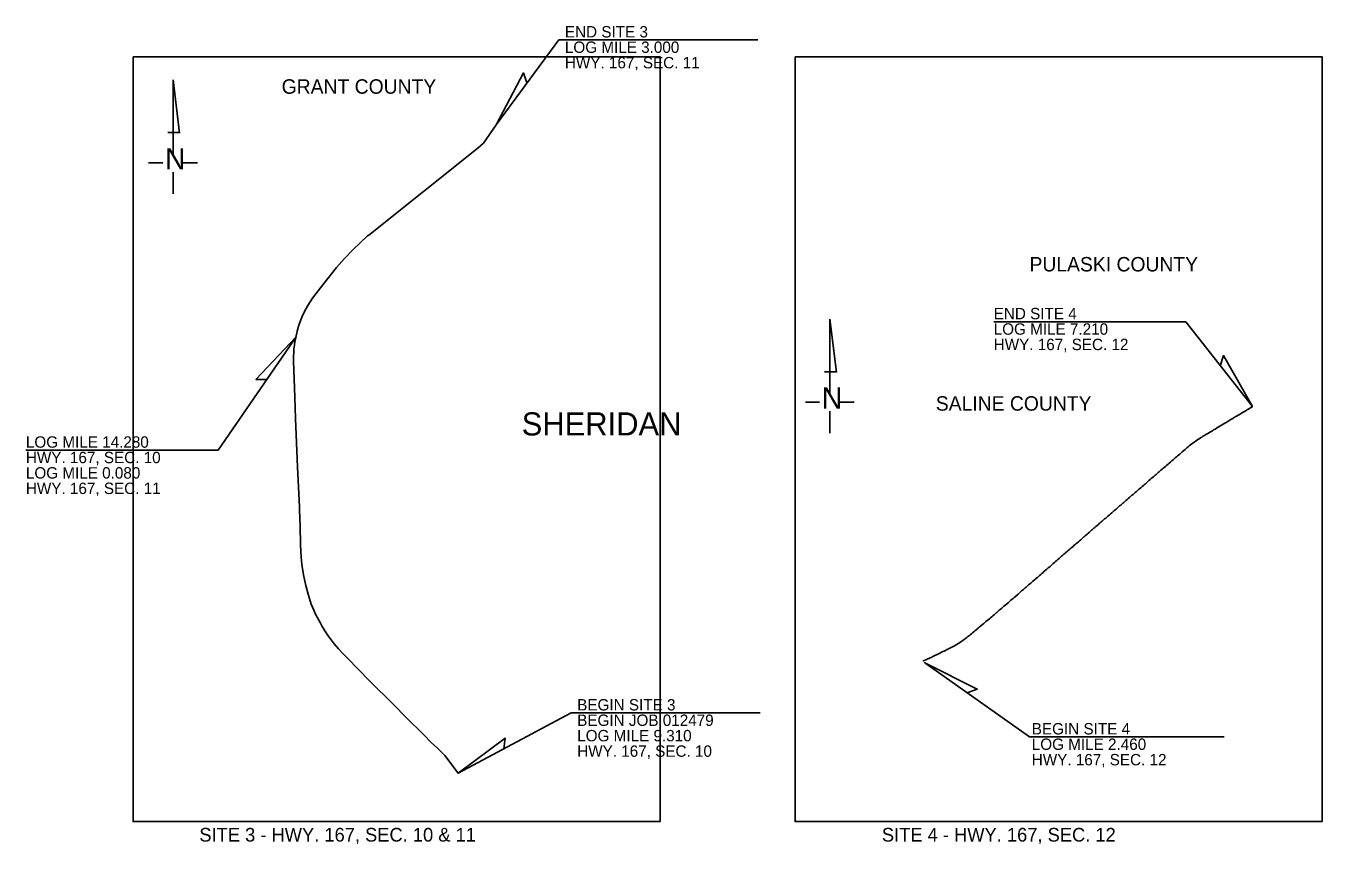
# Model space of a CAD drawing. Extents: x 10700 to 22009, y 10612 to 15552.
# Drawn here: x 14510 to 17352, y 10612 to 12407 of the extents above; entities that cross this region are included whole.
import ezdxf

# ---------------------------------------------------------------- set-up
doc = ezdxf.new("R2010")
doc.units = 0
for name, color, linetype in [('30', 7, 'Continuous'), ('Default', 7, 'Continuous'), ('Level 6', 7, 'Continuous'), ('R_Dimension', 7, 'Continuous'), ('R_Draft', 7, 'Continuous'), ('R_No Plot', 7, 'Continuous')]:
    doc.layers.add(name, color=color, linetype=linetype)

msp = doc.modelspace()

# ---------------------------------------------------------------- linework, layer by layer
at = {"layer": 'Default'}
for points in [[(16962.9, 11401.3), (16964.9, 11402.9), (16967.7, 11405.4), (16970.2, 11407.6), (16972.6, 11409.6), (16975.5, 11412.2), (16977.7, 11414.1), (16980.7, 11416.6), (16983.4, 11419), (16986.5, 11421.6), (16988.3, 11423.2), (16990.6, 11425.2), (16993.1, 11427.3), (16995.2, 11429.2), (16998.9, 11432.4), (17001.5, 11434.6), (17003.8, 11436.6), (17006, 11438.5), (17008.6, 11440.8), (17010.9, 11442.7), (17014.5, 11445.8), (17017, 11447.9), (17019.5, 11450.2), (17023.1, 11453.2), (17025.5, 11455.3), (17027.8, 11457.3), (17030.2, 11459.3), (17032.8, 11461.6), (17035.2, 11463.7), (17037.5, 11465.7), (17040, 11467.8), (17042.9, 11470.3), (17045.4, 11472.4), (17049.2, 11475.7), (17052, 11478.1), (17054, 11479.9), (17056, 11481.6), (17058.3, 11483.6), (17060.7, 11485.6), (17063.8, 11488.1), (17066.5, 11490.2), (17069, 11492.1), (17071.5, 11494), (17073.6, 11495.4), (17076.7, 11497.6), (17079.7, 11499.6), (17082.4, 11501.4), (17085.3, 11503.2), (17088.2, 11505), (17091.1, 11506.8), (17094.1, 11508.6), (17097.5, 11510.6), (17099.9, 11512.1), (17102.9, 11513.8), (17105.8, 11515.6), (17108.7, 11517.3), (17111.6, 11519.1), (17114.3, 11520.7), (17117.5, 11522.6), (17120.2, 11524.2), (17123.2, 11526.1), (17125.9, 11527.6), (17129, 11529.5), (17131.9, 11531.3), (17135.4, 11533.4), (17138.7, 11535.4), (17141.9, 11537.3), (17144.3, 11538.8), (17147.4, 11540.7), (17149.8, 11542.2), (17152.9, 11544.1), (17154.7, 11545.2), (17159.2, 11547.8), (17162, 11549.5), (17166, 11551.9), (17168.4, 11553.4), (17170.9, 11554.8), (17173.1, 11556.2), (17174.9, 11557.2), (17177.5, 11558.7), (17180.4, 11560.5), (17183.4, 11562.3), (17186.3, 11564), (17188.5, 11565.3), (17189.1, 11565.7), (17199.4, 11572.1)], [(16839.6, 11294.4), (16841.9, 11296.4), (16844.4, 11298.7), (16847, 11300.9), (16849, 11302.6), (16851.8, 11305), (16854.3, 11307.1), (16856.5, 11309), (16858.8, 11311.1), (16860.9, 11312.8), (16863.8, 11315.3), (16866, 11317.3), (16868, 11319), (16870.3, 11321), (16873.1, 11323.3), (16875.5, 11325.5), (16877.8, 11327.5), (16880.4, 11329.7), (16882.7, 11331.7), (16885.1, 11333.8), (16887.4, 11335.9), (16891.3, 11339.2), (16893.6, 11341.2), (16895.8, 11343.2), (16898.2, 11345.2), (16900.5, 11347.1), (16902.8, 11349.1), (16905.1, 11351.1), (16908.3, 11354), (16910.6, 11355.9), (16912.9, 11357.9), (16915.1, 11359.8), (16917.5, 11361.9), (16919.9, 11364), (16922.2, 11366), (16924.6, 11368.1), (16927, 11370.1), (16930.6, 11373.3), (16933, 11375.3), (16935.4, 11377.4), (16937.8, 11379.5), (16940.2, 11381.6), (16942.7, 11383.8), (16945.1, 11385.8), (16947.4, 11387.8), (16949.8, 11389.9), (16952.2, 11391.9), (16954.7, 11394.1), (16957.5, 11396.4), (16960.3, 11398.9), (16962.9, 11401.3)], [(16718, 11188.7), (16721.8, 11192), (16723.5, 11193.5), (16725.5, 11195.3), (16728, 11197.4), (16730.3, 11199.5), (16732.8, 11201.6), (16735.4, 11203.9), (16737.9, 11206), (16740.4, 11208.2), (16743.2, 11210.6), (16745.4, 11212.6), (16747.9, 11214.7), (16751.9, 11218.1), (16753.5, 11219.5), (16755.7, 11221.4), (16758, 11223.5), (16760.4, 11225.5), (16762.7, 11227.6), (16765.3, 11229.8), (16767.6, 11231.8), (16770.7, 11234.5), (16772.8, 11236.3), (16775.4, 11238.6), (16778, 11240.8), (16781, 11243.5), (16782.9, 11245.1), (16786.2, 11247.9), (16788.6, 11250.1), (16790.6, 11251.7), (16794.2, 11254.9), (16795.7, 11256.2), (16798.8, 11258.9), (16801.3, 11261.1), (16803.4, 11262.9), (16806.3, 11265.4), (16808.2, 11267.1), (16810.6, 11269.1), (16812.6, 11271), (16814.6, 11272.6), (16818, 11275.6), (16820.4, 11277.7), (16823, 11280), (16825.4, 11282.1), (16828.2, 11284.5), (16829.9, 11286), (16832.1, 11287.9), (16834.3, 11289.9), (16836.9, 11292.1), (16839.6, 11294.4)], [(16637.7, 11119.5), (16638.9, 11120.6), (16641.6, 11122.8), (16644.2, 11125.1), (16646.6, 11127.1), (16650.1, 11130.1), (16652, 11131.7), (16654.5, 11133.8), (16657.3, 11136.2), (16659.3, 11137.8), (16664, 11141.8), (16668.5, 11145.7), (16670.1, 11147.2), (16672.4, 11149.2), (16674.7, 11151.2), (16677, 11153.2), (16679.7, 11155.5), (16685.7, 11160.7), (16688.5, 11163.1), (16691.2, 11165.5), (16693.5, 11167.5), (16697.3, 11170.8), (16699.6, 11172.8), (16701.1, 11174.1), (16703.4, 11176.1), (16706.2, 11178.5), (16708.7, 11180.7), (16710.7, 11182.4), (16713.3, 11184.7), (16716.1, 11187), (16718, 11188.7)], [(16477, 11013.2), (16486.6, 11017.8), (16491.5, 11020.2), (16496.3, 11022.5), (16498.9, 11023.8), (16501.6, 11025.1), (16504.4, 11026.4), (16506.8, 11027.5), (16510, 11029.2), (16512.8, 11030.5), (16515.2, 11031.6), (16518.1, 11033), (16520.8, 11034.4), (16523.5, 11035.7), (16526.3, 11037.1), (16529, 11038.5), (16531.7, 11039.8), (16534.6, 11041.1), (16537.4, 11042.6), (16540.2, 11044.1), (16543.1, 11045.5), (16545.9, 11047.1), (16548.7, 11048.8), (16551.5, 11050.4), (16554.3, 11052.1), (16557, 11053.9), (16559.8, 11055.6), (16562.5, 11057.5), (16565.2, 11059.4), (16567.8, 11061.2), (16570.6, 11063.2), (16573.3, 11065.4), (16575.7, 11067.3), (16578.3, 11069.3), (16580.9, 11071.4), (16583.4, 11073.5), (16585.9, 11075.7), (16588.4, 11077.8), (16590.6, 11079.8), (16593.1, 11081.7), (16598, 11085.9), (16600.5, 11087.9), (16607.9, 11094.1), (16610.4, 11096.1), (16612.8, 11098.2), (16615.3, 11100.3), (16617.8, 11102.4), (16620.3, 11104.5), (16622.8, 11106.6), (16625.3, 11108.7), (16627.8, 11110.8), (16630.4, 11112.9), (16633, 11115.1), (16635.5, 11117.4), (16637.7, 11119.5)]]:
    msp.add_lwpolyline(points, dxfattribs=at)
at = {"layer": 'R_Dimension'}
for p, q in [((16115, 12376.6), (15678.9, 12376.6)), ((17053.5, 11758.3), (16632.2, 11758.3)), ((14931.5, 11476.5), (14510.2, 11476.5)), ((16120.4, 10900), (15705.9, 10900)), ((17137.8, 10847.4), (16710.8, 10847.4))]:
    msp.add_line(p, q, dxfattribs=at)
for points in [[(15678.9, 12376.6), (15541.1, 12190.5), (15601.2, 12304.2), (15608.9, 12282.1)], [(17053.5, 11758.3), (17199.4, 11572.1), (17136.3, 11684.1), (17129.1, 11661.7)], [(14931.5, 11476.5), (15102.5, 11725.3), (15014.5, 11631.6), (15038, 11631.4)], [(16710.8, 10847.4), (16481.2, 11009.9), (16596.2, 10952.3), (16574.2, 10944.1)], [(15705.9, 10900), (15457.8, 10767.6), (15560.8, 10844.6), (15558.3, 10821.2)]]:
    msp.add_lwpolyline(points, dxfattribs=at)
at = {"layer": 'R_Draft'}
for p, q in [((14832.8, 12288.6), (14847.3, 12172.2)), ((14832.8, 12125.9), (14832.8, 12288.6)), ((14821.5, 12173.1), (14847.3, 12173.1)), ((14779.3, 12106.7), (14810.1, 12106.7)), ((14832.8, 12038.6), (14832.8, 12086.5)), ((14853.3, 12106.7), (14886.3, 12106.7)), ((16272.8, 11763.8), (16287.3, 11647.4)), ((16272.8, 11601.1), (16272.8, 11763.8)), ((16261.5, 11648.3), (16287.4, 11648.3)), ((16219.3, 11581.9), (16250.1, 11581.9)), ((16293.3, 11581.9), (16326.3, 11581.9)), ((16272.8, 11513.8), (16272.8, 11561.7))]:
    msp.add_line(p, q, dxfattribs=at)
at = {"layer": 'R_No Plot'}
for points in [[(14745.2, 12339.4), (15900.7, 12339.4), (15900.7, 10661.4), (14745.2, 10661.4)], [(16196.7, 12339.4), (17352.2, 12339.4), (17352.2, 10661.4), (16196.7, 10661.4)]]:
    msp.add_lwpolyline(points, close=True, dxfattribs=at)
for points in [[(15259.5, 11946.4), (15261.8, 11948.4), (15501.6, 12139.7), (15513.5, 12150.3), (15541.1, 12190.5)], [(15104.9, 11737.2), (15107.2, 11745.5), (15109.7, 11752.7), (15116.3, 11769.7), (15119.7, 11777.5), (15124.5, 11786.9), (15128.4, 11793.9), (15138.5, 11809.6), (15145.7, 11819.4), (15161.4, 11839.2), (15191, 11876.9), (15208.4, 11897), (15226.9, 11916.1), (15259.5, 11946.4)], [(15110.2, 11345.2), (15109.9, 11352.1), (15105.9, 11438.8), (15101.6, 11546.2), (15099.8, 11592.4), (15098.5, 11633), (15097.9, 11651.4), (15096.9, 11672.2), (15097.1, 11683.2), (15097.3, 11689.6), (15097.6, 11696), (15097.9, 11698.5), (15098.4, 11702.4), (15100.2, 11713.4), (15104.9, 11737.2)], [(15457.8, 10767.6), (15428.6, 10806.4), (15411.8, 10823.1), (15399.8, 10834.4), (15381.9, 10852.5), (15343.5, 10890.5), (15316.6, 10917.4), (15262.6, 10971.1), (15215, 11020.4), (15204.8, 11030.2), (15195.5, 11040.4), (15186.4, 11051.2), (15179.6, 11060.2), (15173, 11069), (15165.5, 11080.3), (15159.2, 11091.2), (15155.3, 11098.2), (15152.5, 11103.6), (15145.5, 11116.7), (15141.5, 11125.1), (15138.3, 11132), (15135.7, 11138.9), (15129.2, 11160.5), (15123.9, 11179.3), (15119.4, 11199.6), (15116.7, 11216.3), (15115, 11226), (15114.4, 11233.1), (15113.1, 11253.1), (15112.4, 11269.9), (15111.6, 11308.6), (15110.2, 11345.2)]]:
    msp.add_lwpolyline(points, dxfattribs=at)

# ---------------------------------------------------------------- texts
at = {"layer": '30'}
for s, p in [('GRANT COUNTY', (15071, 12258.4)), ('PULASKI COUNTY', (16710.7, 11868.5)), ('SALINE COUNTY', (16505.3, 11563.1))]:
    msp.add_text(s, height=31.68, dxfattribs=at).set_placement(p)
at = {"layer": 'Level 6'}
msp.add_text('SHERIDAN', height=50.69, dxfattribs=at).set_placement((15597.3, 11508.7))
at = {"layer": 'R_Dimension'}
for s, height, p in [('END SITE 3', 25, (15692, 12381.8)), ('LOG MILE 3.000', 25, (15692, 12348)), ('HWY. 167, SEC. 11', 25, (15692, 12314.1)), ('END SITE 4', 25, (16632.2, 11763.6)), ('LOG MILE 7.210', 25, (16632.2, 11729.7)), ('HWY. 167, SEC. 12', 25, (16632.2, 11695.9)), ('LOG MILE 14.280', 25, (14510.2, 11481.8)), ('HWY. 167, SEC. 10', 25, (14510.2, 11447.9)), ('LOG MILE 0.080', 25, (14510.2, 11414.1)), ('HWY. 167, SEC. 11', 25, (14510.2, 11380.2)), ('BEGIN SITE 3', 25, (15719, 10905.3)), ('BEGIN JOB 012479', 25, (15719, 10871.4)), ('LOG MILE 9.310', 25, (15719, 10837.6)), ('BEGIN SITE 4', 25, (16715.7, 10852.7)), ('HWY. 167, SEC. 10', 25, (15719, 10803.7)), ('LOG MILE 2.460', 25, (16715.7, 10818.8)), ('HWY. 167, SEC. 12', 25, (16715.7, 10784.9)), ('SITE 3 - HWY. 167, SEC. 10 & 11', 30, (14890.5, 10617.7)), ('SITE 4 - HWY. 167, SEC. 12', 30, (16387, 10617.7))]:
    msp.add_text(s, height=height, rotation=359.9999, dxfattribs=at).set_placement(p)
at = {"layer": 'R_Draft'}
for p in [(14815.1, 12092.4), (16255.1, 11567.6)]:
    msp.add_text('N', height=46.5, dxfattribs=at).set_placement(p)

doc.saveas('drawing.dxf')
